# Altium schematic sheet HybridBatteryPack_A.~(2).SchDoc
size A4
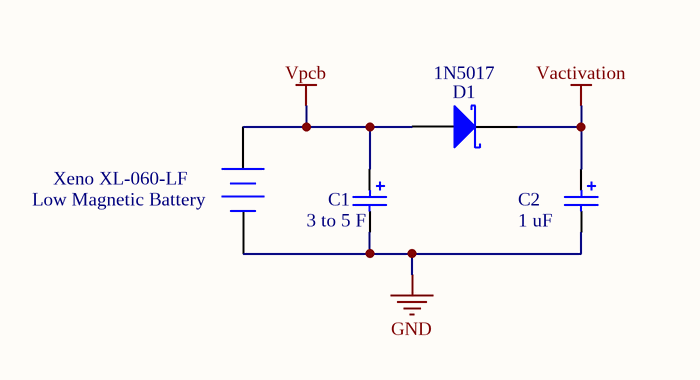
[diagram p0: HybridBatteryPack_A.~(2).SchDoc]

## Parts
C1  value 3 to 5 F  [POLAR0.8]  (hidden comment: Cap Pol2)
C2  value 1 uF  [POLAR0.8]  (hidden comment: Cap Pol2)
D1  1N5017  [DO-204AL]
Xeno_XL-060-LF  Low Magnetic Battery  [BAT-2]

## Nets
GND: C1.2 C2.2 Xeno_XL-060-LF.2(-)
Vactivation: C2.1 D1.2(K)
Vpcb: C1.1 D1.1(A) Xeno_XL-060-LF.1(+)

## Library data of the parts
C1 C2 = Cap Pol2: Polarized Capacitor (Axial)
D1 = Diode 11DQ03: Schottky Rectifier
Xeno_XL-060-LF = Battery: Multicell Battery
